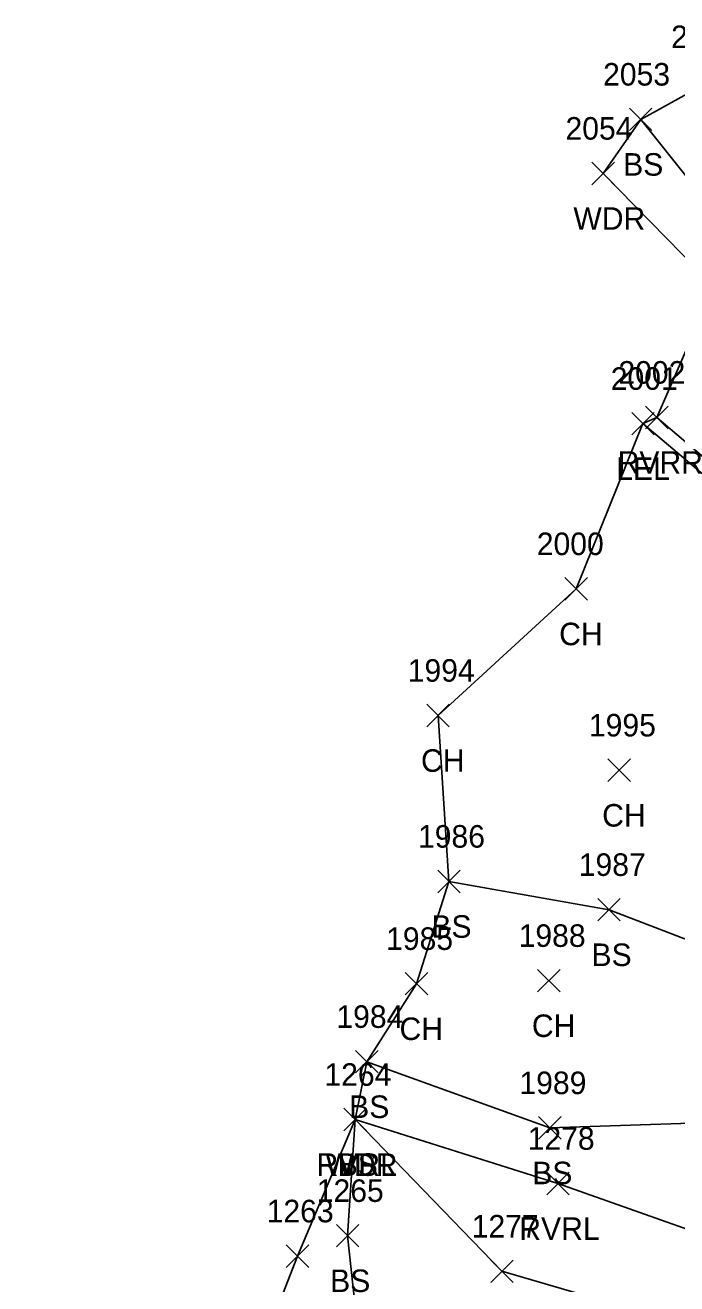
# Model space of a CAD drawing. Extents: x 1600281 to 1602254, y 862855 to 863227.
# Drawn here: x 1601869.4 to 1601927.2, y 863049.8 to 863161.6 of the extents above; entities that cross this region are included whole.
import ezdxf

# ---------------------------------------------------------------- set-up
doc = ezdxf.new("R2010")
doc.units = 0
for name, color, linetype in [('L_A', 7, 'Continuous'), ('L_I', 7, 'Continuous'), ('L_TIC', 7, 'Continuous'), ('LARO', 7, 'Continuous'), ('LAWA', 7, 'Continuous'), ('LAWE', 7, 'Continuous'), ('LELB', 7, 'Continuous'), ('LSOGP', 7, 'Continuous')]:
    doc.layers.add(name, color=color, linetype=linetype)

msp = doc.modelspace()

# ---------------------------------------------------------------- linework, layer by layer
at = {"layer": 'L_TIC'}
for points in [[(1601923.03, 863152.21), (1601925.03, 863154.21)], [(1601925.03, 863152.21), (1601923.03, 863154.21)], [(1601919.69, 863147.41), (1601921.69, 863149.41)], [(1601921.69, 863147.41), (1601919.69, 863149.41)], [(1601924.47, 863125.75), (1601926.47, 863127.75)], [(1601926.47, 863125.75), (1601924.47, 863127.75)], [(1601923.23, 863125.2), (1601925.23, 863127.2)], [(1601925.23, 863125.2), (1601923.23, 863127.2)], [(1601917.3, 863110.53), (1601919.3, 863112.53)], [(1601919.3, 863110.53), (1601917.3, 863112.53)], [(1601905.03, 863099.29), (1601907.03, 863101.29)], [(1601907.03, 863099.29), (1601905.03, 863101.29)], [(1601921.12, 863094.43), (1601923.12, 863096.43)], [(1601923.12, 863094.43), (1601921.12, 863096.43)], [(1601906, 863084.56), (1601908, 863086.56)], [(1601908, 863084.56), (1601906, 863086.56)], [(1601920.22, 863082.05), (1601922.22, 863084.05)], [(1601922.22, 863082.05), (1601920.22, 863084.05)], [(1601903.12, 863075.48), (1601905.12, 863077.48)], [(1601905.12, 863075.48), (1601903.12, 863077.48)], [(1601914.88, 863075.75), (1601916.88, 863077.75)], [(1601916.88, 863075.75), (1601914.88, 863077.75)], [(1601898.7, 863068.56), (1601900.7, 863070.56)], [(1601900.7, 863068.56), (1601898.7, 863070.56)], [(1601897.68, 863063.42), (1601899.68, 863065.42)], [(1601899.68, 863063.42), (1601897.68, 863065.42)], [(1601897.68, 863063.42), (1601899.68, 863065.42)], [(1601899.68, 863063.42), (1601897.68, 863065.42)], [(1601897.68, 863063.42), (1601899.68, 863065.42)], [(1601899.68, 863063.42), (1601897.68, 863065.42)], [(1601914.96, 863062.68), (1601916.96, 863064.68)], [(1601916.96, 863062.68), (1601914.96, 863064.68)], [(1601915.68, 863057.74), (1601917.68, 863059.74)], [(1601917.68, 863057.74), (1601915.68, 863059.74)], [(1601897, 863053.11), (1601899, 863055.11)], [(1601899, 863053.11), (1601897, 863055.11)], [(1601892.55, 863051.3), (1601894.55, 863053.3)], [(1601894.55, 863051.3), (1601892.55, 863053.3)], [(1601910.71, 863049.95), (1601912.71, 863051.95)], [(1601912.71, 863049.95), (1601910.71, 863051.95)]]:
    msp.add_lwpolyline(points, dxfattribs=at)
at = {"layer": 'LARO'}
msp.add_lwpolyline([(1601924.23, 863126.2), (1601937.74, 863114.8), (1601944.42, 863113.1), (1601965.8, 863103.88), (1601978.83, 863086.78)], dxfattribs=at)
at = {"layer": 'LAWA'}
for points in [[(1601930.52, 863138.37), (1601920.69, 863148.41)], [(1601898.68, 863064.42), (1601911.71, 863050.95), (1601935.9, 863043.88), (1601947.49, 863033.02), (1601951.4, 863041.53), (1601951.33, 863053.2), (1601949.99, 863060.09), (1601958.57, 863066.85), (1601964.29, 863071.52), (1601970.83, 863066.79), (1601979.18, 863061.54), (1601987.87, 863058.21), (1601991.58, 863057.22), (1602006.6, 863051.13), (1602014.67, 863047.98), (1602025.68, 863046.6), (1602024.95, 863036.82), (1602020.12, 863030.26)]]:
    msp.add_lwpolyline(points, dxfattribs=at)
at = {"layer": 'LAWE'}
for points in [[(1601925.47, 863126.75), (1601938.5, 863115.68), (1601944.93, 863112.99), (1601966, 863104.79), (1601980.59, 863100.31)], [(1601898.68, 863064.42), (1601916.68, 863058.74), (1601936.52, 863051.72), (1601943.72, 863056.81), (1601947.62, 863066.67), (1601950.71, 863072.59), (1601955.75, 863076.09), (1601965.07, 863075.22), (1601980.92, 863068.62), (1601992.56, 863061.13), (1602010.65, 863053.19), (1602028.1, 863054.19), (1602030.83, 863052.8)]]:
    msp.add_lwpolyline(points, dxfattribs=at)
at = {"layer": 'LELB'}
for points in [[(1601946.14, 863119.33), (1601938.52, 863135.1), (1601924.03, 863153.21)], [(1601907, 863085.56), (1601921.22, 863083.05), (1601929.78, 863079.74), (1601950.61, 863075.65)], [(1601899.7, 863069.56), (1601915.96, 863063.68), (1601934.75, 863064.31), (1601941.46, 863065.97), (1601950.61, 863075.65)], [(1601889.55, 862979.7), (1601879.53, 862980.2), (1601869.36, 862989.31), (1601873.74, 863000.27), (1601884.06, 863016.5), (1601890.01, 863028.23), (1601890.39, 863044.16), (1601893.55, 863052.3), (1601898.68, 863064.42), (1601898, 863054.11), (1601899.32, 863041.88), (1601901.96, 863029.12), (1601931.06, 863015.37), (1601935.9, 863043.88), (1601936.52, 863051.72)]]:
    msp.add_lwpolyline(points, dxfattribs=at)
at = {"layer": 'LSOGP'}
msp.add_lwpolyline([(1601930.07, 863156.54), (1601924.03, 863153.21), (1601920.69, 863148.41), (1601930.52, 863138.37), (1601925.47, 863126.75), (1601924.23, 863126.2), (1601918.3, 863111.53), (1601906.03, 863100.29), (1601907, 863085.56), (1601904.12, 863076.48), (1601899.7, 863069.56), (1601898.68, 863064.42), (1601893.55, 863052.3), (1601890.39, 863044.16)], dxfattribs=at)

# ---------------------------------------------------------------- texts
at = {"layer": 'L_A'}
for s, p in [('BS', (1601922.47, 863148.21)), ('WDR', (1601918.05, 863143.41)), ('LEL', (1601921.86, 863121.2)), ('RVRR', (1601921.98, 863121.75)), ('CH', (1601916.79, 863106.53)), ('CH', (1601904.52, 863095.29)), ('CH', (1601920.61, 863090.43)), ('BS', (1601905.44, 863080.56)), ('BS', (1601919.66, 863078.05)), ('CH', (1601902.61, 863071.48)), ('CH', (1601914.37, 863071.75)), ('BS', (1601898.14, 863064.56)), ('RVRL', (1601895.24, 863059.42)), ('WDR', (1601896.04, 863059.42)), ('BS', (1601897.12, 863059.42)), ('BS', (1601914.4, 863058.68)), ('RVRL', (1601913.25, 863053.74)), ('BS', (1601896.45, 863049.11))]:
    msp.add_text(s, height=2, dxfattribs=at).set_placement(p)
at = {"layer": 'L_I'}
for s, p in [('2052', (1601926.73, 863159.54)), ('2053', (1601920.69, 863156.21)), ('2054', (1601917.35, 863151.41)), ('2001', (1601921.37, 863129.2)), ('2002', (1601922.05, 863129.75)), ('2000', (1601914.8, 863114.53)), ('1994', (1601903.34, 863103.29)), ('1995', (1601919.43, 863098.43)), ('1986', (1601904.25, 863088.56)), ('1987', (1601918.53, 863086.05)), ('1985', (1601901.42, 863079.48)), ('1988', (1601913.19, 863079.75)), ('1984', (1601897, 863072.56)), ('1264', (1601895.94, 863067.42)), ('1264', (1601895.94, 863067.42)), ('1264', (1601895.94, 863067.42)), ('1989', (1601913.26, 863066.68)), ('1278', (1601913.99, 863061.74)), ('1265', (1601895.26, 863057.11)), ('1263', (1601890.81, 863055.3)), ('1277', (1601909.02, 863053.95))]:
    msp.add_text(s, height=2, dxfattribs=at).set_placement(p)

doc.saveas('drawing.dxf')
